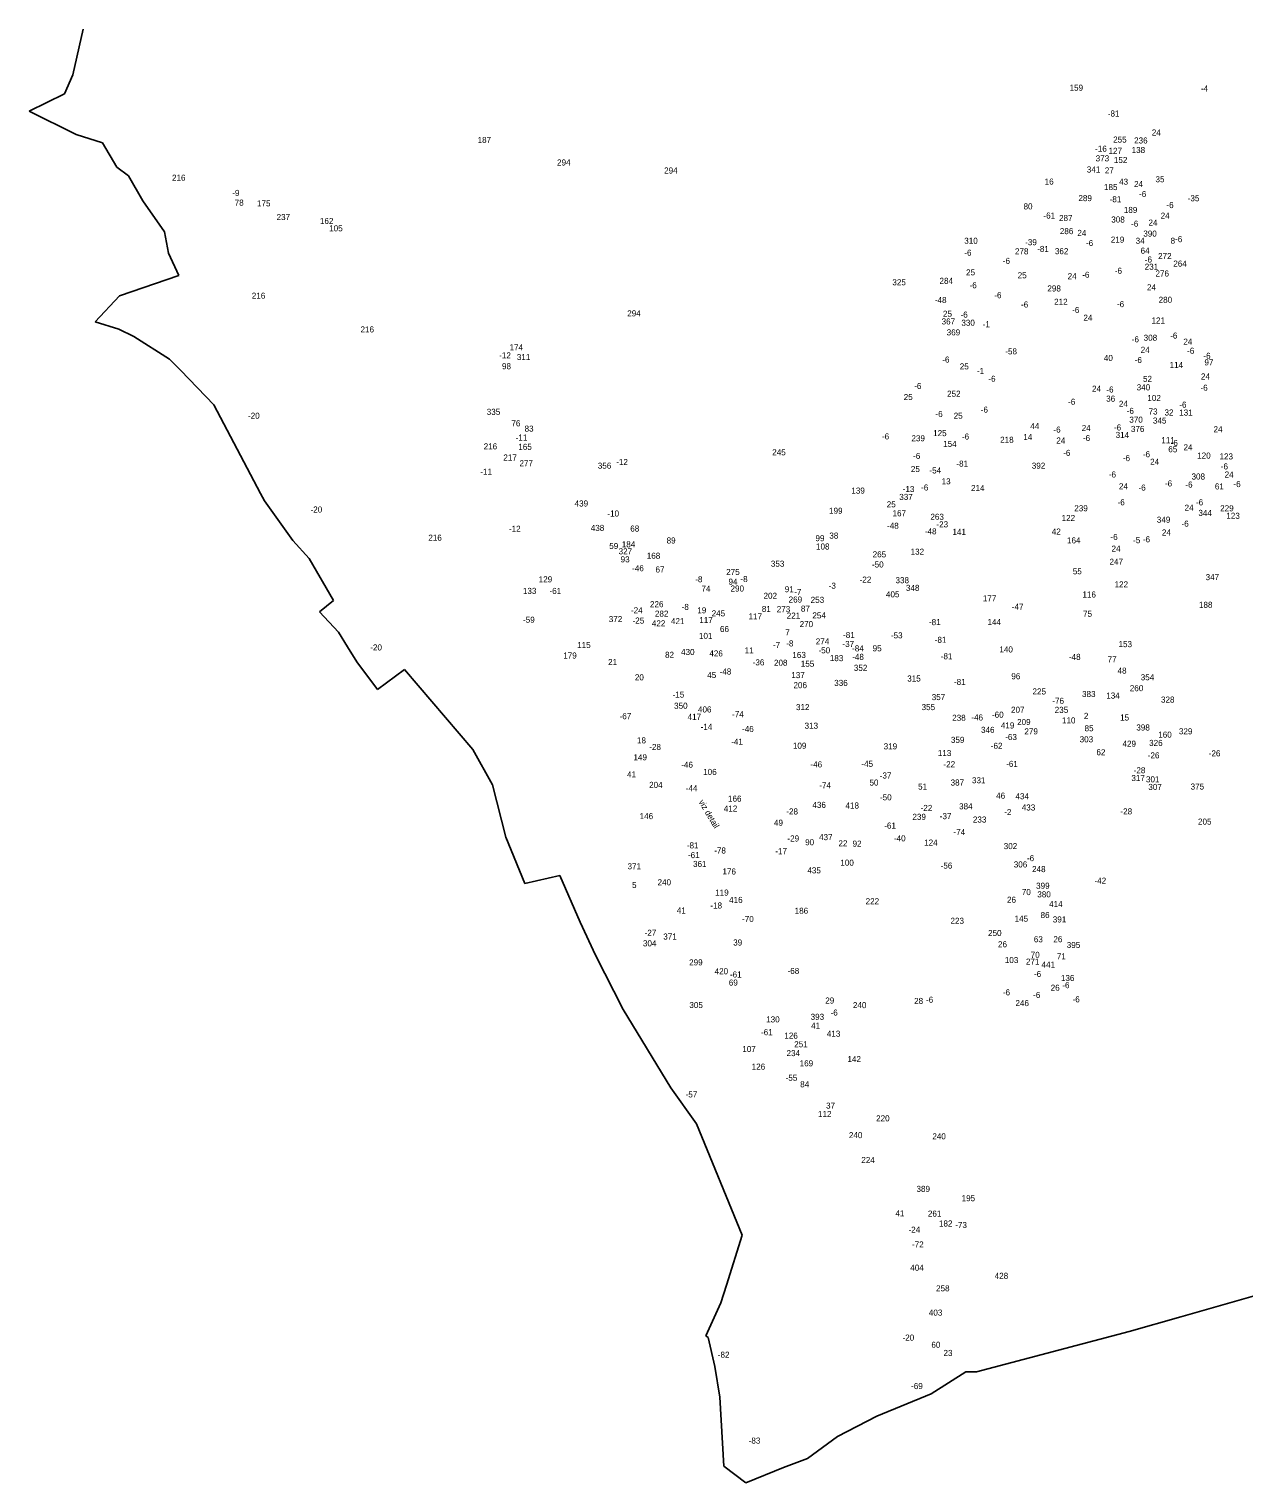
# Model space of a CAD drawing. Extents: x -783331 to -781808, y -970520 to -969319.
# Drawn here: x -783331 to -782328, y -970520 to -969319 of the extents above; entities that cross this region are included whole.
import ezdxf

# ---------------------------------------------------------------- set-up
doc = ezdxf.new("R2010")
doc.units = 0
for name, color, linetype in [('Vrstva 13', 7, 'Continuous'), ('Vrstva 15', 7, 'Continuous'), ('Vrstva 24', 7, 'Continuous')]:
    doc.layers.add(name, color=color, linetype=linetype)

msp = doc.modelspace()

# ---------------------------------------------------------------- linework, layer by layer
at = {"layer": 'Vrstva 13'}
for p, q in [((-783295.27, -969356.79), (-783286.61, -969318.95)), ((-783302.23, -969372.49), (-783295.27, -969356.79)), ((-783331.36, -969386.74), (-783302.23, -969372.49)), ((-783292.52, -969406.16), (-783331.36, -969386.74)), ((-783270.68, -969412.96), (-783292.52, -969406.16)), ((-783258.93, -969433.08), (-783270.68, -969412.96)), ((-783249.14, -969440.28), (-783258.93, -969433.08)), ((-783237.33, -969460.76), (-783249.14, -969440.28)), ((-783219.6, -969486.34), (-783237.33, -969460.76)), ((-783216.12, -969503.99), (-783219.6, -969486.34)), ((-783207.54, -969522.48), (-783216.12, -969503.99)), ((-783256.74, -969539.31), (-783207.54, -969522.48)), ((-783276.8, -969560.88), (-783256.74, -969539.31)), ((-783257.3, -969566.96), (-783276.8, -969560.88)), ((-783244.76, -969572.78), (-783257.3, -969566.96)), ((-783215.47, -969591.64), (-783244.76, -969572.78)), ((-783205.92, -969600.87), (-783215.47, -969591.64)), ((-783178.66, -969629.28), (-783205.92, -969600.87)), ((-783140.31, -969702.61), (-783178.66, -969629.28)), ((-783136.99, -969708.6), (-783140.31, -969702.61)), ((-783113.37, -969741.38), (-783136.99, -969708.6)), ((-783100.1, -969756.36), (-783113.37, -969741.38)), ((-783079.88, -969790.93), (-783100.1, -969756.36)), ((-783091.45, -969800.31), (-783079.88, -969790.93)), ((-783075.67, -969817.07), (-783091.45, -969800.31)), ((-783068.31, -969829.29), (-783075.67, -969817.07)), ((-783060.7, -969841.51), (-783068.31, -969829.29)), ((-783043.63, -969864.42), (-783060.7, -969841.51)), ((-783021.3, -969847.82), (-783043.63, -969864.42)), ((-782964.83, -969914.11), (-783021.3, -969847.82)), ((-782948.65, -969943.13), (-782964.83, -969914.11)), ((-782937.56, -969986.47), (-782948.65, -969943.13)), ((-782921.87, -970024.8), (-782937.56, -969986.47)), ((-782892.99, -970018.21), (-782921.87, -970024.8)), ((-782876.07, -970056.7), (-782892.99, -970018.21)), ((-782863.45, -970083.89), (-782876.07, -970056.7)), ((-782840.64, -970128.89), (-782863.45, -970083.89)), ((-782801.24, -970193.6), (-782840.64, -970128.89)), ((-782780.12, -970223.14), (-782801.24, -970193.6)), ((-782742.43, -970315.26), (-782780.12, -970223.14)), ((-782755.22, -970356.46), (-782742.43, -970315.26)), ((-782759.9, -970371.1), (-782755.22, -970356.46)), ((-782293.56, -970357.89), (-782379.82, -970382.57)), ((-782772.28, -970398.46), (-782759.9, -970371.1)), ((-782379.82, -970382.57), (-782422.63, -970394.89)), ((-782422.63, -970394.89), (-782548.61, -970428.07)), ((-782770.51, -970399.67), (-782772.28, -970398.46)), ((-782764.93, -970423.59), (-782770.51, -970399.67)), ((-782760.72, -970449), (-782764.93, -970423.59)), ((-782557.66, -970428.12), (-782586.14, -970446.17)), ((-782548.61, -970428.07), (-782557.66, -970428.12)), ((-782757.57, -970506.02), (-782760.72, -970449)), ((-782586.14, -970446.17), (-782631.04, -970464.71)), ((-782631.04, -970464.71), (-782663.48, -970481.62)), ((-782663.48, -970481.62), (-782688.4, -970499.71)), ((-782688.4, -970499.71), (-782708.14, -970507.16)), ((-782739.21, -970519.86), (-782757.57, -970506.02)), ((-782708.14, -970507.16), (-782739.21, -970519.86))]:
    msp.add_line(p, q, dxfattribs=at)

# ---------------------------------------------------------------- texts
at = {"layer": 'Vrstva 15'}
for s, p in [('159', (-782471.852, -969369.85)), ('-4', (-782363.358, -969370.52)), ('-81', (-782440.247, -969391.2)), ('187', (-782960.86, -969413.06)), ('255', (-782435.863, -969412.71)), ('236', (-782418.535, -969413.45)), ('24', (-782403.902, -969406.9)), ('-16', (-782450.729, -969420.27)), ('127', (-782439.66, -969422.02)), ('138', (-782420.59, -969421.33)), ('294', (-782895.223, -969431.64)), ('294', (-782806.753, -969438.27)), ('341', (-782457.578, -969437.44)), ('373', (-782450.282, -969428.25)), ('27', (-782442.702, -969438.2)), ('152', (-782435.25, -969429.57)), ('216', (-783213.292, -969444.23)), ('16', (-782492.432, -969447.39)), ('43', (-782430.931, -969447.56)), ('24', (-782418.612, -969449.4)), ('35', (-782400.873, -969445.48)), ('-9', (-783163.522, -969456.78)), ('289', (-782464.535, -969461.09)), ('185', (-782443.4, -969451.95)), ('-81', (-782438.767, -969461.98)), ('-6', (-782414.432, -969457.69)), ('-35', (-782374.24, -969461.17)), ('78', (-783161.502, -969464.78)), ('175', (-783143.07, -969465.41)), ('80', (-782509.854, -969467.93)), ('-61', (-782493.428, -969475.47)), ('189', (-782427.022, -969470.84)), ('24', (-782396.592, -969475.58)), ('-6', (-782391.832, -969466.84)), ('237', (-783126.892, -969476.72)), ('162', (-783091.122, -969479.96)), ('105', (-783083.45, -969485.99)), ('287', (-782480.562, -969477.49)), ('308', (-782437.393, -969478.74)), ('-6', (-782421.022, -969482.18)), ('24', (-782406.652, -969481.31)), ('310', (-782558.84, -969496.31)), ('-39', (-782508.532, -969497.5)), ('286', (-782479.885, -969488.34)), ('24', (-782465.412, -969489.81)), ('-6', (-782458.272, -969498.19)), ('219', (-782437.792, -969495.36)), ('34', (-782417.232, -969496.31)), ('390', (-782410.945, -969490.38)), ('8', (-782388.403, -969496.26)), ('-6', (-782384.692, -969494.96)), ('-6', (-782558.772, -969506.14)), ('278', (-782516.952, -969505.03)), ('-81', (-782498.587, -969503.05)), ('362', (-782483.974, -969504.88)), ('64', (-782413.143, -969504.46)), ('272', (-782398.722, -969508.94)), ('25', (-782557.353, -969522.39)), ('-6', (-782526.992, -969512.91)), ('-6', (-782434.462, -969521.07)), ('231', (-782409.76, -969517.73)), ('-6', (-782409.712, -969511.78)), ('276', (-782400.884, -969523.34)), ('264', (-782386.143, -969515.16)), ('325', (-782618.233, -969530.58)), ('284', (-782579.282, -969529.41)), ('-6', (-782554.462, -969533.05)), ('25', (-782514.713, -969524.81)), ('298', (-782490.184, -969535.7)), ('24', (-782473.402, -969525.53)), ('-6', (-782461.372, -969524.43)), ('24', (-782407.872, -969534.72)), ('216', (-783147.362, -969541.69)), ('-48', (-782583.128, -969545.25)), ('-6', (-782534.012, -969541.26)), ('212', (-782484.59, -969546.69)), ('280', (-782398.264, -969545.06)), ('294', (-782837.243, -969556.28)), ('25', (-782576.433, -969556.58)), ('-6', (-782561.932, -969557.29)), ('-6', (-782511.952, -969548.93)), ('-6', (-782469.712, -969553.5)), ('-6', (-782432.712, -969548.65)), ('216', (-783057.562, -969569.53)), ('367', (-782577.544, -969562.94)), ('330', (-782561.214, -969564.02)), ('-1', (-782543.597, -969565.22)), ('24', (-782460.392, -969559.86)), ('121', (-782404.158, -969562.19)), ('369', (-782573.356, -969571.99)), ('-6', (-782420.472, -969577.72)), ('308', (-782410.643, -969576.43)), ('-6', (-782388.722, -969574.62)), ('24', (-782377.882, -969579.63)), ('-12', (-782943.047, -969590.94)), ('174', (-782934.448, -969584.25)), ('311', (-782928.418, -969592.35)), ('-6', (-782576.992, -969594.4)), ('-58', (-782524.96, -969587.64)), (' 40', (-782445.341, -969593.09)), ('-6', (-782418.052, -969594.81)), ('24', (-782413.072, -969586.4)), ('-6', (-782374.732, -969587.14)), ('-6', (-782361.282, -969591.31)), ('98', (-782940.694, -969599.92)), ('25', (-782562.553, -969600.08)), ('-1', (-782548.347, -969603.79)), ('114', (-782389.196, -969598.84)), ('97', (-782360.444, -969596.75)), ('-6', (-782600.172, -969616.26)), ('-6', (-782538.912, -969610.3)), ('24', (-782453.292, -969618.48)), ('-6', (-782441.452, -969619.17)), ('340', (-782416.401, -969617.39)), ('52', (-782411.183, -969610.39)), ('-6', (-782363.702, -969617.69)), ('24', (-782363.322, -969608.43)), ('25', (-782608.843, -969625.39)), ('252', (-782573.043, -969622.69)), ('-6', (-782473.062, -969629.26)), ('36', (-782441.595, -969626.7)), ('24', (-782431.102, -969630.97)), ('102', (-782407.58, -969626.15)), ('-6', (-782381.182, -969631.68)), ('-20', (-783150.52, -969640.8)), ('335', (-782953.303, -969637.61)), ('-6', (-782582.622, -969639.44)), ('25', (-782567.583, -969640.82)), ('-6', (-782545.202, -969635.8)), ('-6', (-782424.642, -969636.8)), ('73', (-782406.602, -969637.34)), ('32', (-782393.413, -969638.15)), ('131', (-782381.268, -969638.21)), ('76', (-782932.914, -969647.11)), ('83', (-782922.053, -969651.48)), ('125', (-782584.57, -969655.21)), ('44', (-782504.279, -969649.43)), ('-6', (-782485.172, -969652.27)), ('24', (-782461.792, -969650.91)), ('-6', (-782435.142, -969650.52)), ('370', (-782422.492, -969644.08)), ('376', (-782421.154, -969651.73)), ('345', (-782402.991, -969644.83)), ('24', (-782352.922, -969651.96)), ('216', (-782955.842, -969666.15)), ('-11', (-782929.384, -969658.83)), ('165', (-782927.222, -969666.53)), ('-6', (-782626.822, -969657.91)), ('239', (-782602.485, -969659.43)), ('154', (-782576.268, -969664.08)), ('-6', (-782560.772, -969657.99)), ('218', (-782529.19, -969660.68)), ('14', (-782510.068, -969658.37)), ('24', (-782482.762, -969661.31)), ('-6', (-782460.822, -969659.27)), ('314', (-782433.798, -969656.69)), ('111', (-782396.054, -969661)), ('-6', (-782388.312, -969663.31)), ('24', (-782377.712, -969666.87)), ('217', (-782939.58, -969675.35)), ('-12', (-782846.357, -969679.04)), ('245', (-782717.471, -969671.04)), ('-6', (-782601.122, -969674.06)), ('-6', (-782477.102, -969671.52)), ('-6', (-782427.822, -969675.85)), ('-6', (-782411.292, -969672.62)), ('24', (-782405.272, -969678.84)), ('65', (-782390.284, -969668.5)), ('120', (-782366.43, -969673.74)), ('123', (-782348, -969674.44)), ('-11', (-782958.604, -969687.07)), ('277', (-782926.262, -969680.05)), ('356', (-782861.565, -969682.07)), ('25', (-782602.943, -969684.87)), ('-54', (-782587.568, -969686.01)), ('-81', (-782565.337, -969680.41)), ('392', (-782503.024, -969682.08)), ('-6', (-782439.402, -969689.34)), ('308', (-782371.073, -969691.03)), ('-6', (-782346.912, -969682.69)), ('24', (-782343.732, -969689.41)), ('139', (-782652.112, -969702.68)), ('-13', (-782609.637, -969701.39)), ('-6', (-782594.482, -969700.08)), ('13', (-782577.54, -969695)), ('214', (-782553.278, -969700.54)), ('24', (-782431.102, -969699.13)), ('-6', (-782414.902, -969700.17)), ('-6', (-782393.062, -969696.75)), ('-6', (-782376.162, -969697.7)), ('61', (-782351.812, -969699.22)), ('-6', (-782336.462, -969697.32)), ('439', (-782880.703, -969713.32)), ('25', (-782622.873, -969714)), ('337', (-782612.522, -969707.89)), ('-6', (-782432.182, -969712.33)), ('-6', (-782367.422, -969712.33)), ('-20', (-783098.87, -969718.3)), ('-10', (-782853.628, -969721.6)), ('199', (-782670.524, -969719.31)), ('167', (-782618.072, -969721.36)), ('263', (-782586.804, -969724.3)), ('122', (-782478.42, -969725.27)), ('239', (-782467.955, -969717.26)), ('349', (-782399.753, -969726.7)), ('24', (-782376.842, -969716.81)), ('344', (-782365.409, -969721.08)), ('229', (-782347.435, -969717.27)), ('123', (-782342.34, -969723.48)), ('-12', (-782934.937, -969734.18)), ('438', (-782867.371, -969733.5)), ('68', (-782834.724, -969734.03)), ('38', (-782670.303, -969739.85)), ('-48', (-782622.608, -969731.72)), ('-48', (-782591.388, -969736.3)), ('-23', (-782581.83, -969730.54)), ('141', (-782568.596, -969736.75)), ('42', (-782486.521, -969736.51)), ('24', (-782395.572, -969737.28)), ('-6', (-782379.382, -969730)), ('216', (-783001.572, -969741.56)), ('59', (-782852.095, -969748.43)), ('184', (-782841.758, -969747.05)), ('89', (-782804.705, -969743.87)), ('99', (-782681.756, -969741.99)), ('108', (-782681.31, -969748.86)), ('164', (-782473.97, -969743.8)), ('-6', (-782438.072, -969741.02)), ('24', (-782437.172, -969750.63)), ('-5', (-782419.35, -969743.62)), ('-6', (-782411.292, -969742.92)), ('327', (-782844.362, -969752.82)), ('93', (-782842.694, -969759.47)), ('168', (-782821.112, -969756.51)), ('353', (-782718.593, -969763.03)), ('-50', (-782635.09, -969763.7)), ('265', (-782634.524, -969755.33)), ('132', (-782603.16, -969753.12)), ('247', (-782438.84, -969761.43)), ('-46', (-782833.19, -969766.8)), ('67', (-782813.874, -969767.82)), ('-8', (-782781.05, -969775.91)), ('275', (-782755.482, -969769.89)), ('-8', (-782743.73, -969775.74)), ('55', (-782469.163, -969769.33)), ('347', (-782359.46, -969774.14)), ('133', (-782923.43, -969785.52)), ('129', (-782910.372, -969775.97)), ('-61', (-782901.458, -969785.53)), ('74', (-782775.88, -969783.58)), ('94', (-782753.583, -969777.9)), ('290', (-782751.895, -969783.56)), ('91', (-782707.122, -969784.13)), ('-7', (-782699.29, -969786.39)), ('-3', (-782670.83, -969781.23)), ('-22', (-782645.29, -969776.2)), ('338', (-782615.653, -969776.67)), ('348', (-782607.011, -969783.03)), ('122', (-782434.67, -969780.13)), ('226', (-782818.435, -969796.48)), ('-8', (-782792.31, -969798.77)), ('202', (-782724.623, -969789.55)), ('269', (-782703.926, -969792.67)), ('253', (-782685.703, -969792.9)), ('405', (-782623.52, -969788.32)), ('177', (-782543.509, -969791.73)), ('-47', (-782519.578, -969798.62)), ('116', (-782461.22, -969788.49)), ('188', (-782364.97, -969797.02)), ('-59', (-782923.322, -969809.36)), ('372', (-782852.502, -969808.8)), ('-24', (-782834.178, -969801.55)), ('-25', (-782832.88, -969810.01)), ('282', (-782814.383, -969804.33)), ('421', (-782801.088, -969810.5)), ('19', (-782779.342, -969801.52)), ('117', (-782777.717, -969809.63)), ('245', (-782767.501, -969804.08)), ('117', (-782737.047, -969806.61)), ('81', (-782726.02, -969800.44)), ('273', (-782713.732, -969800.62)), ('221', (-782705.48, -969805.94)), ('87', (-782693.772, -969800.19)), ('254', (-782684.312, -969805.77)), ('-81', (-782588.007, -969811.32)), ('144', (-782539.646, -969811.23)), ('75', (-782460.722, -969804.44)), ('422', (-782816.921, -969812.32)), ('101', (-782778.008, -969822.68)), ('66', (-782760.646, -969817.03)), ('7', (-782706.692, -969819.8)), ('270', (-782694.842, -969812.97)), ('-81', (-782658.947, -969821.94)), ('-53', (-782619.45, -969822.24)), ('-20', (-783049.53, -969832.25)), ('115', (-782878.598, -969830.26)), ('430', (-782792.771, -969835.97)), ('11', (-782740.318, -969834.71)), ('-7', (-782716.84, -969830.23)), ('-8', (-782705.9, -969828.91)), ('274', (-782681.53, -969827.29)), ('-50', (-782679.24, -969834.56)), ('-37', (-782659.45, -969829.35)), ('-84', (-782651.498, -969833)), ('95', (-782634.524, -969832.94)), ('-81', (-782583.227, -969825.92)), ('140', (-782529.798, -969833.9)), ('153', (-782431.41, -969829.49)), ('179', (-782890.112, -969838.9)), ('21', (-782853.06, -969844.33)), ('82', (-782805.993, -969838.3)), ('426', (-782769.403, -969837.18)), ('-36', (-782733.622, -969844.55)), ('208', (-782716.033, -969844.88)), ('163', (-782700.822, -969838.42)), ('155', (-782693.87, -969845.69)), ('183', (-782669.88, -969841.05)), ('-48', (-782651.418, -969840.01)), ('-81', (-782578.257, -969839.51)), ('-48', (-782472.378, -969840.03)), ('77', (-782440.372, -969841.96)), ('20', (-782830.924, -969856.93)), ('45', (-782771.141, -969855.02)), ('-48', (-782760.918, -969852.12)), ('137', (-782701.7, -969855.07)), ('352', (-782650.033, -969849.08)), ('315', (-782605.94, -969857.88)), ('96', (-782519.936, -969856.02)), ('48', (-782432.191, -969851.37)), ('354', (-782413.042, -969856.86)), ('-15', (-782799.847, -969871.14)), ('206', (-782699.925, -969863.38)), ('336', (-782666.245, -969861.52)), ('-81', (-782567.317, -969860.73)), ('225', (-782502.453, -969868.58)), ('383', (-782461.533, -969870.69)), ('260', (-782422.095, -969865.87)), ('350', (-782798.534, -969880.38)), ('406', (-782778.812, -969883.46)), ('312', (-782697.84, -969881.52)), ('355', (-782594.083, -969881.51)), (' 357', (-782587.572, -969873.24)), ('207', (-782520.212, -969883.68)), ('-76', (-782486.071, -969876.3)), ('235', (-782484.113, -969883.79)), ('134', (-782441.528, -969872)), ('328', (-782396.303, -969875.3)), ('-67', (-782843.571, -969889)), ('417', (-782787.358, -969889.56)), ('-74', (-782750.598, -969887.36)), ('238', (-782568.803, -969890.31)), ('-46', (-782552.99, -969890.06)), ('-60', (-782535.952, -969887.75)), ('209', (-782515.185, -969893.82)), ('110', (-782478.108, -969892.5)), ('2', (-782460.003, -969888.76)), ('15', (-782430.09, -969890.09)), ('-14', (-782776.626, -969897.8)), ('-46', (-782742.41, -969899.64)), ('313', (-782690.75, -969896.86)), ('346', (-782544.983, -969900.31)), ('419', (-782528.6, -969896.68)), ('-63', (-782525.002, -969906.24)), ('279', (-782509.164, -969901.56)), ('85', (-782459.463, -969898.97)), ('398', (-782416.704, -969898.35)), ('160', (-782398.592, -969904.25)), ('329', (-782381.515, -969901.48)), ('18', (-782829.2, -969908.98)), ('-28', (-782819.06, -969914.44)), ('-41', (-782751.355, -969910.08)), ('109', (-782700.382, -969913.42)), ('319', (-782625.402, -969913.93)), ('113', (-782580.648, -969919.45)), ('359', (-782569.855, -969908.57)), ('-62', (-782536.912, -969913.46)), ('303', (-782463.533, -969908.1)), ('62', (-782449.654, -969918.8)), ('429', (-782428.133, -969911.76)), ('326', (-782406.135, -969911.09)), ('-26', (-782356.872, -969919.73)), ('149', (-782832.1, -969922.94)), ('-46', (-782792.62, -969929.08)), ('-46', (-782685.88, -969928.85)), ('-45', (-782643.848, -969928.38)), ('-22', (-782576.01, -969928.69)), ('-61', (-782524.198, -969928.4)), ('-26', (-782407.232, -969921.39)), ('41', (-782837.418, -969937.15)), ('106', (-782774.522, -969935.04)), ('50', (-782637.134, -969943.84)), ('-37', (-782628.68, -969938.01)), ('387', (-782570.112, -969943.81)), ('331', (-782552.45, -969941.92)), ('317', (-782420.78, -969940.13)), ('-28', (-782418.87, -969933.67)), ('301', (-782408.74, -969941.15)), ('204', (-782819.131, -969945.76)), ('-44', (-782788.896, -969948.48)), ('-74', (-782678.588, -969946.03)), ('-50', (-782628.48, -969956)), ('51', (-782596.98, -969947.16)), ('46', (-782532.463, -969954.62)), ('434', (-782516.569, -969955.13)), ('307', (-782406.762, -969947.46)), ('375', (-782371.862, -969947.13)), ('412', (-782757.498, -969965.33)), ('166', (-782753.984, -969957.11)), ('-28', (-782705.86, -969967.71)), ('436', (-782684.283, -969962.27)), ('418', (-782656.948, -969962.81)), ('-22', (-782594.92, -969964.8)), ('384', (-782563.102, -969963.45)), ('433', (-782511.341, -969964.42)), ('-28', (-782429.81, -969967.64)), ('146', (-782826.96, -969971.58)), ('49', (-782716.023, -969976.99)), ('-61', (-782624.928, -969979.36)), ('239', (-782601.655, -969972.14)), ('-37', (-782579.07, -969971.58)), ('233', (-782551.713, -969974.38)), ('-2', (-782525.81, -969968.2)), ('205', (-782365.753, -969976.09)), ('-29', (-782704.882, -969990.03)), ('437', (-782678.77, -969988.92)), ('-40', (-782616.948, -969989.86)), ('-74', (-782567.748, -969984.76)), ('-81', (-782787.997, -969995.72)), ('-61', (-782787.078, -970003.76)), ('-78', (-782765.409, -969999.95)), ('-17', (-782714.937, -970000.5)), ('90', (-782690.265, -969993.11)), ('22', (-782662.773, -969994.01)), ('92', (-782651.114, -969994.28)), ('124', (-782591.958, -969993.42)), ('302', (-782526.253, -969996.33)), ('371', (-782837, -970012.97)), ('361', (-782782.872, -970011.05)), ('100', (-782661.18, -970010)), ('-56', (-782578.332, -970012.42)), ('306', (-782517.945, -970011.46)), ('-6', (-782507.052, -970006.27)), ('248', (-782502.821, -970015.33)), ('240', (-782812.191, -970026.25)), ('176', (-782758.592, -970017.28)), ('435', (-782688.431, -970016.37)), ('-42', (-782451.248, -970024.87)), ('5', (-782833.253, -970028.47)), ('119', (-782764.6, -970034.71)), ('70', (-782511.272, -970034.31)), ('399', (-782499.486, -970029.06)), ('380', (-782498.494, -970036.19)), ('41', (-782796.318, -970049.51)), ('-18', (-782768.557, -970045.38)), ('416', (-782753.08, -970040.74)), ('186', (-782698.942, -970049.73)), ('222', (-782640.293, -970041.86)), ('26', (-782523.515, -970040.64)), ('414', (-782488.726, -970044.22)), ('-70', (-782742.39, -970056.55)), ('223', (-782570.213, -970058.02)), ('145', (-782517.288, -970056.24)), ('86', (-782495.805, -970053.28)), ('391', (-782485.702, -970056.9)), ('-27', (-782822.88, -970067.91)), ('371', (-782807.49, -970071.02)), ('39', (-782749.705, -970075.95)), ('250', (-782539.164, -970068.08)), ('63', (-782501.334, -970073.27)), ('26', (-782485.205, -970073.25)), ('304', (-782824.271, -970076.63)), ('26', (-782530.965, -970077.4)), ('70', (-782503.962, -970086.13)), ('71', (-782482.33, -970087.3)), ('299', (-782786.096, -970092.39)), ('420', (-782765.041, -970099.69)), ('-68', (-782704.802, -970099.45)), ('103', (-782525.32, -970090.45)), ('271', (-782507.9, -970091.76)), ('69', (-782753.316, -970109.05)), ('-61', (-782752.418, -970102.37)), ('-6', (-782501.252, -970101.92)), ('136', (-782478.982, -970105.28)), ('-6', (-782477.842, -970111.2)), ('29', (-782673.645, -970123.89)), ('-6', (-782590.442, -970123.18)), ('-6', (-782526.952, -970117.13)), ('-6', (-782501.932, -970119.28)), ('26', (-782487.455, -970113.31)), ('-6', (-782469.372, -970122.92)), ('305', (-782785.923, -970127.62)), ('-6', (-782669.272, -970133.81)), ('240', (-782650.831, -970127.69)), ('28', (-782600.253, -970124.23)), ('246', (-782516.553, -970126.01)), ('130', (-782722.48, -970139.48)), ('41', (-782685.318, -970144.64)), ('-61', (-782726.748, -970150.03)), ('126', (-782707.482, -970152.88)), ('251', (-782699.31, -970159.96)), ('413', (-782672.338, -970151.29)), ('107', (-782742.2, -970163.96)), ('234', (-782705.642, -970167.32)), ('126', (-782734.422, -970178.48)), ('169', (-782694.804, -970175.77)), ('142', (-782655.338, -970172.27)), ('-55', (-782706.39, -970187.67)), ('84', (-782694.352, -970193.09)), ('-57', (-782789.03, -970201.45)), ('112', (-782679.668, -970217.6)), ('37', (-782672.982, -970210.7)), ('220', (-782631.654, -970221.18)), ('240', (-782654.141, -970235.08)), ('240', (-782585.221, -970236.08)), ('224', (-782643.892, -970255.58)), ('389', (-782598.295, -970279.47)), ('195', (-782561.002, -970287.16)), ('41', (-782615.738, -970299.77)), ('261', (-782588.882, -970299.91)), ('-24', (-782604.888, -970313.17)), ('182', (-782579.75, -970308.05)), ('-73', (-782566.289, -970309.31)), ('-72', (-782602.009, -970325.37)), ('404', (-782603.419, -970344.54)), ('428', (-782533.701, -970351.28)), ('258', (-782582.133, -970361.58)), ('403', (-782588.06, -970381.66)), ('-20', (-782609.83, -970402.3)), ('60', (-782585.985, -970408.23)), ('-82', (-782762.43, -970416.46)), ('23', (-782575.973, -970414.99)), ('-69', (-782602.734, -970442.35)), ('-83', (-782736.91, -970487.4))]:
    msp.add_text(s, height=5, dxfattribs=at).set_placement(p)
msp.add_text('viz detail', height=5, rotation=300.607144, dxfattribs=at).set_placement((-782778.48, -969957.34))
at = {"layer": 'Vrstva 24'}
for s, p in [('395', (-782474.184, -970078)), ('441', (-782494.986, -970094.16)), ('393', (-782685.744, -970137.32))]:
    msp.add_text(s, height=5, dxfattribs=at).set_placement(p)

doc.saveas('drawing.dxf')
